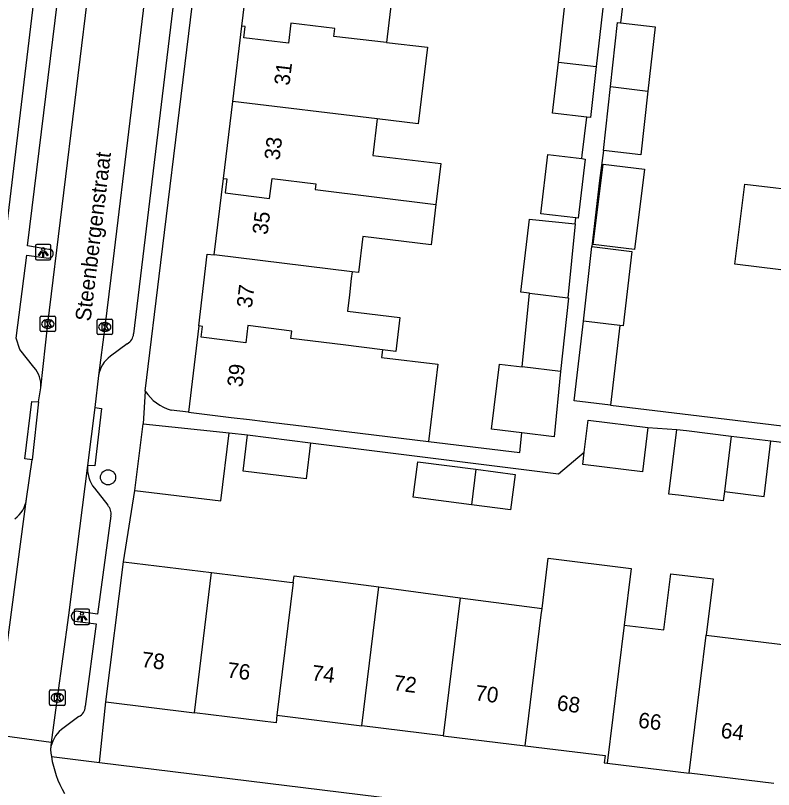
# Model space of a CAD drawing. Extents: x 158087 to 159494, y 382905 to 383981.
# Drawn here: x 158309.9 to 158358.9, y 383277.6 to 383327.6 of the extents above; entities that cross this region are included whole.
import ezdxf

# ---------------------------------------------------------------- set-up
doc = ezdxf.new("R2010")
doc.units = 0
for name, color, linetype in [('IMGEO_Boom', 7, 'Continuous'), ('IMGEO_Kolk', 7, 'Continuous'), ('IMGEO_Lichtpunt', 7, 'Continuous'), ('IMGEO_Openbare_ruimte_label', 7, 'Continuous'), ('IMGEO_Pand', 7, 'Continuous'), ('IMGEO_Pand_nummerreeks', 7, 'Continuous'), ('IMGEO_Rijbaan_lokaal_open', 7, 'Continuous'), ('IMGEO_Voetpad_open', 7, 'Continuous')]:
    doc.layers.add(name, color=color, linetype=linetype)

msp = doc.modelspace()

# ---------------------------------------------------------------- linework, layer by layer
at = {"layer": 'IMGEO_Boom'}
msp.add_circle((158315.86, 383297.724), 0.489, dxfattribs=at)
at = {"layer": 'IMGEO_Kolk'}
for p, q in [((158311.466, 383307.213), (158311.466, 383308.065)), ((158311.541, 383308.139), (158312.393, 383308.139)), ((158311.954, 383307.919), (158311.979, 383307.919)), ((158312.467, 383308.065), (158312.467, 383307.213)), ((158315.149, 383307.018), (158315.149, 383307.87)), ((158315.224, 383307.944), (158316.076, 383307.944)), ((158316.15, 383307.87), (158316.15, 383307.018)), ((158311.977, 383307.359), (158311.952, 383307.359)), ((158315.637, 383307.724), (158315.662, 383307.724)), ((158312.393, 383307.139), (158311.541, 383307.139)), ((158316.076, 383306.944), (158315.224, 383306.944)), ((158315.66, 383307.164), (158315.635, 383307.164)), ((158312.082, 383283.059), (158312.082, 383283.911)), ((158312.157, 383283.985), (158313.009, 383283.985)), ((158313.083, 383283.911), (158313.083, 383283.059)), ((158312.57, 383283.765), (158312.595, 383283.765)), ((158313.009, 383282.985), (158312.157, 383282.985)), ((158312.593, 383283.205), (158312.568, 383283.205))]:
    msp.add_line(p, q, dxfattribs=at)
for points in [[(158311.466, 383307.213), (158311.466, 383308.065)], [(158311.541, 383308.139), (158312.393, 383308.139)], [(158311.787, 383307.839), (158311.91, 383307.839), (158311.91, 383307.688), (158312.04, 383307.839), (158312.204, 383307.839), (158312.058, 383307.688), (158312.211, 383307.439), (158312.059, 383307.439), (158311.974, 383307.603), (158311.91, 383307.536), (158311.91, 383307.439), (158311.787, 383307.439), (158311.787, 383307.839)], [(158312.467, 383308.065), (158312.467, 383307.213)], [(158315.149, 383307.018), (158315.149, 383307.87)], [(158315.224, 383307.944), (158316.076, 383307.944)], [(158316.15, 383307.87), (158316.15, 383307.018)], [(158315.47, 383307.644), (158315.593, 383307.644), (158315.593, 383307.493), (158315.723, 383307.644), (158315.887, 383307.644), (158315.741, 383307.493), (158315.894, 383307.244), (158315.742, 383307.244), (158315.657, 383307.408), (158315.593, 383307.341), (158315.593, 383307.244), (158315.47, 383307.244), (158315.47, 383307.644)], [(158312.393, 383307.139), (158311.541, 383307.139)], [(158316.076, 383306.944), (158315.224, 383306.944)], [(158312.082, 383283.059), (158312.082, 383283.911)], [(158312.157, 383283.985), (158313.009, 383283.985)], [(158313.083, 383283.911), (158313.083, 383283.059)], [(158312.403, 383283.685), (158312.526, 383283.685), (158312.526, 383283.534), (158312.656, 383283.685), (158312.82, 383283.685), (158312.674, 383283.534), (158312.827, 383283.285), (158312.675, 383283.285), (158312.59, 383283.449), (158312.526, 383283.382), (158312.526, 383283.285), (158312.403, 383283.285), (158312.403, 383283.685)], [(158313.009, 383282.985), (158312.157, 383282.985)]]:
    msp.add_lwpolyline(points, dxfattribs=at)
for centre, start, end in [((158311.543, 383308.063), 91.552, 178.448), ((158311.543, 383308.063), 91.552, 178.448), ((158312.391, 383308.063), 1.552, 88.448), ((158312.391, 383308.063), 1.552, 88.448), ((158315.226, 383307.868), 91.552, 178.448), ((158315.226, 383307.868), 91.552, 178.448), ((158316.074, 383307.868), 1.552, 88.448), ((158316.074, 383307.868), 1.552, 88.448), ((158311.543, 383307.215), 181.552, 268.448), ((158311.543, 383307.215), 181.552, 268.448), ((158312.391, 383307.215), 271.552, 358.448), ((158312.391, 383307.215), 271.552, 358.448), ((158315.226, 383307.02), 181.552, 268.448), ((158315.226, 383307.02), 181.552, 268.448), ((158316.074, 383307.02), 271.552, 358.448), ((158316.074, 383307.02), 271.552, 358.448), ((158312.159, 383283.909), 91.552, 178.448), ((158312.159, 383283.909), 91.552, 178.448), ((158313.007, 383283.909), 1.552, 88.448), ((158313.007, 383283.909), 1.552, 88.448), ((158312.159, 383283.061), 181.552, 268.448), ((158312.159, 383283.061), 181.552, 268.448), ((158313.007, 383283.061), 271.552, 358.448), ((158313.007, 383283.061), 271.552, 358.448)]:
    msp.add_arc(centre, 0.0765, start, end, dxfattribs=at)
for centre, major_axis, ratio, start_param, end_param in [((158311.953, 383307.639), (-0.387, 0.002), 0.722429, 4.712389, 7.853982), ((158311.978, 383307.639), (-0.39, 0.002), 0.717154, 1.570796, 4.712389), ((158315.636, 383307.444), (-0.387, 0.002), 0.722429, 4.712389, 7.853982), ((158315.661, 383307.444), (-0.39, 0.002), 0.717154, 1.570796, 4.712389), ((158312.569, 383283.485), (-0.387, 0.002), 0.722429, 4.712389, 7.853982), ((158312.594, 383283.485), (-0.39, 0.002), 0.717154, 1.570796, 4.712389)]:
    msp.add_ellipse(centre, major_axis=major_axis, ratio=ratio, start_param=start_param, end_param=end_param, dxfattribs=at)
at = {"layer": 'IMGEO_Lichtpunt'}
for p, q in [((158311.17, 383312.674), (158311.17, 383311.867)), ((158311.17, 383312.674), (158311.17, 383311.867)), ((158312.072, 383312.769), (158311.264, 383312.769)), ((158312.072, 383312.769), (158311.264, 383312.769)), ((158312.166, 383311.867), (158312.166, 383312.674)), ((158312.166, 383311.867), (158312.166, 383312.674)), ((158311.264, 383311.773), (158312.072, 383311.773)), ((158311.264, 383311.773), (158312.072, 383311.773)), ((158313.672, 383289.117), (158313.672, 383288.31)), ((158313.672, 383289.117), (158313.672, 383288.31)), ((158314.574, 383289.212), (158313.766, 383289.212)), ((158314.574, 383289.212), (158313.766, 383289.212)), ((158314.668, 383288.31), (158314.668, 383289.117)), ((158314.668, 383288.31), (158314.668, 383289.117)), ((158313.766, 383288.216), (158314.574, 383288.216)), ((158313.766, 383288.216), (158314.574, 383288.216))]:
    msp.add_line(p, q, dxfattribs=at)
for points in [[(158311.544, 383312.338), (158311.583, 383312.31), (158311.395, 383312.048), (158311.357, 383312.075), (158311.544, 383312.338)], [(158311.756, 383312.31), (158311.794, 383312.337), (158311.981, 383312.075), (158311.942, 383312.047), (158311.756, 383312.31)], [(158311.646, 383312.29), (158311.693, 383312.29), (158311.693, 383311.968), (158311.646, 383311.968), (158311.646, 383312.29)], [(158314.046, 383288.781), (158314.085, 383288.753), (158313.897, 383288.491), (158313.859, 383288.518), (158314.046, 383288.781)], [(158314.148, 383288.733), (158314.195, 383288.733), (158314.195, 383288.411), (158314.148, 383288.411), (158314.148, 383288.733)], [(158314.258, 383288.753), (158314.296, 383288.78), (158314.483, 383288.518), (158314.444, 383288.49), (158314.258, 383288.753)]]:
    msp.add_lwpolyline(points, dxfattribs=at)
for centre in [(158311.669, 383312.472), (158314.171, 383288.915)]:
    msp.add_circle(centre, 0.0994, dxfattribs=at)
for centre, start, end in [((158311.264, 383312.674), 90, 180), ((158311.264, 383312.674), 90, 180), ((158312.072, 383312.674), 0, 90), ((158312.072, 383312.674), 0, 90), ((158311.264, 383311.867), 180, 270), ((158311.264, 383311.867), 180, 270), ((158312.072, 383311.867), 270, 0), ((158312.072, 383311.867), 270, 360), ((158313.766, 383289.117), 90, 180), ((158313.766, 383289.117), 90, 180), ((158314.574, 383289.117), 0, 90), ((158314.574, 383289.117), 0, 90), ((158313.766, 383288.31), 180, 270), ((158313.766, 383288.31), 180, 270), ((158314.574, 383288.31), 270, 0), ((158314.574, 383288.31), 270, 360)]:
    msp.add_arc(centre, 0.0946, start, end, dxfattribs=at)
at = {"layer": 'IMGEO_Pand'}
for points in [[(158324.506, 383326.874), (158325.112, 383331.865)], [(158334.451, 383330.729), (158333.853, 383325.819)], [(158344.968, 383324.558), (158345.521, 383329.455), (158347.981, 383329.177)], [(158347.981, 383329.177), (158347.41, 383324.281)], [(158323.917, 383322.017), (158324.506, 383326.874)], [(158333.853, 383325.819), (158330.459, 383326.204), (158330.518, 383326.73), (158327.679, 383327.076), (158327.521, 383325.78), (158324.642, 383326.13), (158324.729, 383326.847), (158324.506, 383326.874)], [(158348.338, 383322.971), (158348.797, 383327.106), (158348.99, 383327.085)], [(158348.99, 383327.085), (158351.219, 383326.837), (158350.756, 383322.675)], [(158333.853, 383325.819), (158336.5, 383325.518), (158335.897, 383320.559), (158333.253, 383320.881)], [(158346.805, 383320.998), (158344.593, 383321.248), (158344.968, 383324.558)], [(158344.968, 383324.558), (158347.41, 383324.281)], [(158347.41, 383324.281), (158347.053, 383320.97), (158346.805, 383320.998)], [(158347.879, 383318.843), (158348.338, 383322.971)], [(158348.338, 383322.971), (158350.756, 383322.675)], [(158350.756, 383322.675), (158350.3, 383318.574), (158347.879, 383318.843)], [(158323.313, 383317.036), (158323.917, 383322.017)], [(158333.253, 383320.881), (158323.917, 383322.017)], [(158333.253, 383320.881), (158332.967, 383318.531), (158337.376, 383317.995), (158337.056, 383315.364)], [(158346.099, 383314.486), (158343.833, 383314.762), (158344.299, 383318.587), (158346.479, 383318.321)], [(158346.479, 383318.321), (158346.712, 383318.293), (158346.247, 383314.468), (158346.099, 383314.486)], [(158349.892, 383312.439), (158347.22, 383312.766), (158347.856, 383317.968), (158350.528, 383317.642), (158349.892, 383312.439)], [(158322.714, 383312.099), (158323.313, 383317.036)], [(158323.313, 383317.036), (158323.533, 383317.009), (158323.422, 383316.098), (158326.301, 383315.748), (158326.459, 383317.044), (158329.298, 383316.698), (158329.251, 383316.314), (158337.056, 383315.364)], [(158361.179, 383310.917), (158360.758, 383310.969), (158356.381, 383311.504), (158357.013, 383316.676), (158361.39, 383316.141)], [(158337.056, 383315.364), (158336.737, 383312.745), (158332.328, 383313.282), (158332.046, 383310.963), (158331.64, 383311.012)], [(158343.098, 383309.619), (158342.542, 383309.687), (158343.105, 383314.404), (158343.308, 383314.383), (158346.06, 383314.095)], [(158346.06, 383314.095), (158345.586, 383309.316)], [(158346.584, 383307.823), (158347.14, 383312.633)], [(158347.14, 383312.633), (158349.717, 383312.318), (158349.162, 383307.509), (158348.937, 383307.536)], [(158321.72, 383307.513), (158322.277, 383312.152), (158322.714, 383312.099)], [(158331.64, 383311.012), (158322.714, 383312.099)], [(158331.64, 383311.012), (158331.586, 383310.569), (158331.459, 383309.519), (158331.331, 383308.47), (158334.723, 383308.057), (158334.457, 383305.864), (158333.604, 383305.968)], [(158342.626, 383304.87), (158343.098, 383309.619)], [(158343.098, 383309.619), (158345.586, 383309.316)], [(158345.586, 383309.316), (158345.62, 383309.312), (158345.116, 383304.567)], [(158348.343, 383302.396), (158345.989, 383302.668), (158346.584, 383307.823)], [(158348.937, 383307.536), (158346.584, 383307.823)], [(158321.72, 383307.513), (158321.051, 383301.936)], [(158333.604, 383305.968), (158331.064, 383306.277), (158327.669, 383306.69), (158327.731, 383307.172), (158324.897, 383307.53), (158324.759, 383306.422), (158321.88, 383306.772), (158321.966, 383307.48), (158321.72, 383307.513)], [(158348.937, 383307.536), (158348.343, 383302.396)], [(158333.604, 383305.968), (158333.544, 383305.474), (158337.18, 383305.032), (158336.574, 383300.048)], [(158342.607, 383300.596), (158340.657, 383300.833), (158341.17, 383305.047), (158342.626, 383304.87)], [(158345.116, 383304.567), (158342.626, 383304.87)], [(158345.116, 383304.567), (158344.698, 383300.341), (158342.607, 383300.596)], [(158321.051, 383301.936), (158323.817, 383301.599), (158324.996, 383301.456), (158326.015, 383301.332), (158329.075, 383300.96), (158330.397, 383300.799), (158336.574, 383300.048)], [(158346.641, 383299.358), (158346.894, 383301.425), (158350.756, 383300.952)], [(158317.597, 383296.881), (158318.121, 383301.188)], [(158318.121, 383301.188), (158323.695, 383300.599)], [(158350.756, 383300.952), (158350.403, 383298.079), (158346.542, 383298.553), (158346.641, 383299.358)], [(158355.706, 383296.805), (158355.67, 383296.509), (158355.633, 383296.214), (158352.742, 383296.569), (158352.118, 383296.645), (158352.63, 383300.821)], [(158352.63, 383300.821), (158353.254, 383300.744), (158356.146, 383300.389)], [(158317.597, 383296.881), (158323.16, 383296.204), (158323.695, 383300.599)], [(158328.953, 383299.96), (158328.67, 383297.633), (158324.591, 383298.129), (158324.876, 383300.474)], [(158324.876, 383300.474), (158328.953, 383299.96)], [(158356.146, 383300.389), (158355.706, 383296.805)], [(158356.146, 383300.389), (158358.702, 383300.076)], [(158355.706, 383296.805), (158358.262, 383296.491), (158358.702, 383300.076)], [(158339.359, 383295.953), (158335.589, 383296.441), (158335.886, 383298.732), (158339.64, 383298.245)], [(158339.64, 383298.245), (158342.175, 383297.917), (158341.878, 383295.626), (158339.359, 383295.953)], [(158339.64, 383298.245), (158339.359, 383295.953)], [(158343.916, 383289.251), (158344.27, 383292.136), (158344.314, 383292.497), (158349.669, 383291.84), (158349.22, 383288.179)], [(158315.728, 383283.211), (158316.86, 383292.266)], [(158316.86, 383292.266), (158322.548, 383291.569)], [(158321.439, 383282.512), (158322.548, 383291.569)], [(158322.548, 383291.569), (158326.038, 383291.141), (158327.6, 383290.95), (158327.829, 383290.922)], [(158327.829, 383290.922), (158327.882, 383291.358), (158333.358, 383290.638)], [(158349.22, 383288.179), (158351.795, 383287.863), (158352.241, 383291.498), (158354.974, 383291.163), (158354.933, 383290.829), (158354.528, 383287.529)], [(158327.829, 383290.922), (158326.778, 383282.346)], [(158332.259, 383281.675), (158333.358, 383290.638)], [(158333.358, 383290.638), (158338.623, 383289.946)], [(158338.623, 383289.946), (158337.53, 383281.029)], [(158338.623, 383289.946), (158341.442, 383289.576), (158343.916, 383289.251)], [(158342.829, 383280.38), (158343.865, 383288.835), (158343.916, 383289.251)], [(158349.22, 383288.179), (158348.127, 383279.261)], [(158353.435, 383278.611), (158354.528, 383287.529)], [(158354.528, 383287.529), (158359.987, 383286.861)], [(158315.728, 383283.211), (158321.439, 383282.512)], [(158326.778, 383282.346), (158326.719, 383281.865), (158321.439, 383282.512)], [(158326.778, 383282.346), (158332.259, 383281.675)], [(158337.53, 383281.029), (158332.259, 383281.675)], [(158337.53, 383281.029), (158342.829, 383280.38)], [(158342.829, 383280.38), (158347.989, 383279.748), (158347.932, 383279.285), (158348.127, 383279.261)], [(158348.127, 383279.261), (158353.435, 383278.611)], [(158358.896, 383277.942), (158353.435, 383278.611)]]:
    msp.add_lwpolyline(points, dxfattribs=at)
at = {"layer": 'IMGEO_Rijbaan_lokaal_open'}
for points in [[(158311.518, 383303.514), (158311.969, 383307.638), (158314.752, 383330.407), (158314.836, 383331.281)], [(158318.494, 383330.81), (158318.371, 383329.873), (158316.168, 383311.673), (158315.649, 383307.444), (158315.249, 383304.301)], [(158315.249, 383304.301), (158315, 383302.244)], [(158311.373, 383302.595), (158311.518, 383303.514)], [(158311.373, 383302.595), (158310.963, 383298.859)], [(158315, 383302.244), (158314.537, 383298.49)], [(158310.599, 383296.34), (158310.963, 383298.859)], [(158314.537, 383298.49), (158313.297, 383288.816), (158312.582, 383283.485), (158312.182, 383280.589)], [(158308.549, 383281.081), (158308.979, 383284.118), (158310.599, 383296.34)], [(158312.182, 383280.589), (158308.549, 383281.081)], [(158312.182, 383280.589), (158312.137, 383280.142)], [(158312.137, 383280.142), (158312.162, 383279.909), (158312.195, 383279.677)]]:
    msp.add_lwpolyline(points, dxfattribs=at)
msp.add_arc((158318.868, 383280.741), 6.757, 189.0569, 210.5717, dxfattribs=at)
at = {"layer": 'IMGEO_Voetpad_open'}
for points in [[(158311.12, 383391.319), (158317.588, 383381.778), (158317.256, 383379.22), (158312.006, 383336.596), (158309.154, 383312.647), (158308.137, 383304.132)], [(158318.267, 383303.291), (158319.275, 383311.616), (158322.163, 383335.236), (158325.326, 383361.214), (158327.974, 383383.09)], [(158319.142, 383331.72), (158320.096, 383330.577), (158320.273, 383329.879), (158317.513, 383306.998)], [(158312.032, 383312.454), (158310.647, 383312.686), (158312.903, 383330.955)], [(158349.18, 383328.725), (158348.99, 383327.085)], [(158346.479, 383318.321), (158346.501, 383318.548), (158346.805, 383320.998)], [(158347.879, 383318.843), (158347.634, 383316.911), (158347.14, 383312.633)], [(158346.06, 383314.095), (158346.099, 383314.486)], [(158311.072, 383304.835), (158310.165, 383305.989), (158309.922, 383306.708), (158310.606, 383312.07), (158312.02, 383311.894)], [(158317.107, 383306.353), (158316.026, 383305.544)], [(158318.267, 383303.291), (158318.121, 383301.188)], [(158310.963, 383298.859), (158310.476, 383298.914), (158310.935, 383302.623), (158311.373, 383302.595)], [(158348.343, 383302.396), (158359.978, 383300.987)], [(158315, 383302.244), (158315.432, 383302.168), (158315.002, 383298.46), (158314.537, 383298.49)], [(158321.051, 383301.936), (158319.936, 383302.071)], [(158350.756, 383300.952), (158352.63, 383300.821)], [(158323.695, 383300.599), (158324.876, 383300.474)], [(158336.574, 383300.048), (158342.481, 383299.327), (158342.607, 383300.596)], [(158328.953, 383299.96), (158344.976, 383297.943), (158346.641, 383299.358)], [(158358.702, 383300.076), (158366.696, 383299.14)], [(158314.977, 383297.02), (158315.837, 383295.921)], [(158316.86, 383292.266), (158317.597, 383296.881)], [(158316.045, 383295.232), (158315.169, 383288.885), (158313.795, 383289.067)], [(158313.72, 383288.422), (158315.099, 383288.264), (158314.388, 383282.91)], [(158315.314, 383279.287), (158315.728, 383283.211)], [(158313.977, 383282.262), (158312.854, 383281.421)], [(158312.195, 383279.677), (158315.314, 383279.287)], [(158315.314, 383279.287), (158346.553, 383275.453), (158358.185, 383274.026), (158358.16, 383273.883), (158368.763, 383272.542)]]:
    msp.add_lwpolyline(points, dxfattribs=at)
for centre, radius, start, end in [((158312.043, 383312.174), 0.281, 265.3987, 92.1462), ((158316.69, 383307.066), 0.825, 300.3172, 355.3054), ((158317.053, 383304.038), 1.823, 124.2796, 171.7014), ((158309.746, 383303.652), 1.777, 355.5566, 41.7551), ((158320.759, 383304.949), 2.993, 213.631, 254.0371), ((158316.574, 383298.299), 2.046, 174.6357, 218.6912), ((158308.663, 383296.605), 1.954, 306.7493, 352.2081), ((158315.311, 383295.386), 0.75, 348.1453, 45.4514), ((158313.806, 383288.739), 0.328, 91.9403, 254.7946), ((158313.655, 383282.921), 0.734, 296.0797, 359.1497), ((158314.045, 383279.913), 1.922, 128.3037, 173.1468)]:
    msp.add_arc(centre, radius, start, end, dxfattribs=at)

# ---------------------------------------------------------------- texts
at = {"layer": 'IMGEO_Openbare_ruimte_label'}
msp.add_text('Steenbergenstraat', height=1, rotation=83.0526, dxfattribs=at).set_placement((158314.725, 383307.769))
at = {"layer": 'IMGEO_Pand_nummerreeks'}
for s, rotation, p in [('31', 83.0663, (158327.583, 383323.008)), ('33', 83.0663, (158326.944, 383318.181)), ('35', 83.0789, (158326.171, 383313.366)), ('37', 83.1591, (158325.158, 383308.634)), ('39', 83.1591, (158324.544, 383303.513)), ('78', 353.0171, (158317.984, 383285.473)), ('76', 353.0156, (158323.517, 383284.795)), ('74', 353.0156, (158328.985, 383284.614)), ('72', 353.0175, (158334.265, 383283.968)), ('70', 353.0156, (158339.553, 383283.32)), ('68', 353.0156, (158344.836, 383282.673)), ('66', 352.9354, (158350.091, 383281.556)), ('64', 352.9371, (158355.428, 383280.895))]:
    msp.add_text(s, height=1, rotation=rotation, dxfattribs=at).set_placement(p)

doc.saveas('drawing.dxf')
